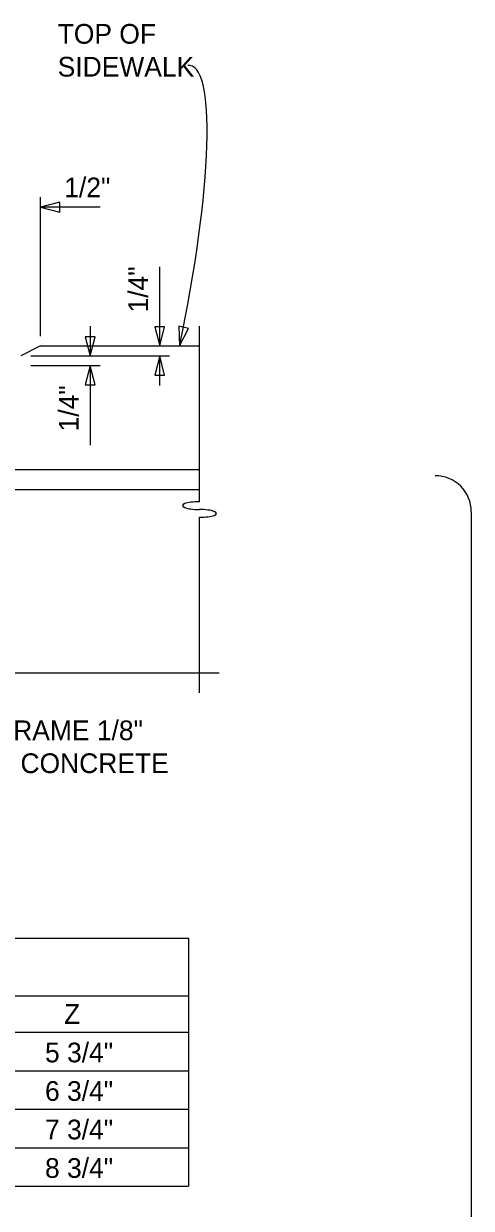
# Model space of a CAD drawing. Extents: x 19590 to 20151, y 19944 to 20103.
# Drawn here: x 19703.76 to 19715.03, y 20049.76 to 20079.64 of the extents above; entities that cross this region are included whole.
import ezdxf

# ---------------------------------------------------------------- set-up
doc = ezdxf.new("R2010")
doc.units = 0
for name, color, linetype in [('DETAIL_PR', 7, 'Continuous'), ('DETAIL_TEXT_DIMEN_PR', 7, 'Continuous'), ('Level 1', 7, 'Continuous')]:
    doc.layers.add(name, color=color, linetype=linetype)

# ---------------------------------------------------------------- blocks, each defined once
blk = doc.blocks.new('BRE')
at = {"layer": 'DETAIL_PR'}
for centre, ratio, start_param, end_param in [((0, 0.098), 0.230206, 4.712389, 7.853982), ((0, -0.098), 0.230204, 1.570796, 4.712389)]:
    blk.add_ellipse(centre, major_axis=(-0.427, 0), ratio=ratio, start_param=start_param, end_param=end_param, dxfattribs=at)

msp = doc.modelspace()

# ---------------------------------------------------------------- linework, layer by layer
at = {"layer": 'DETAIL_PR'}
for p, q in [((19704.186, 20071.509), (19703.686, 20071.259)), ((19704.186, 20071.509), (19703.686, 20071.259)), ((19704.186, 20071.509), (19708.186, 20071.509)), ((19704.186, 20071.509), (19708.186, 20071.509)), ((19708.186, 20068.384), (19699.129, 20068.384)), ((19708.186, 20068.384), (19699.129, 20068.384)), ((19708.186, 20067.884), (19699.629, 20067.884)), ((19708.186, 20067.884), (19699.629, 20067.884))]:
    msp.add_line(p, q, dxfattribs=at)
at = {"layer": 'DETAIL_TEXT_DIMEN_PR'}
for p, q in [((19704.186, 20071.759), (19704.186, 20075.259)), ((19704.186, 20071.759), (19704.186, 20075.259)), ((19704.668, 20075.133), (19704.186, 20075.009)), ((19704.668, 20075.133), (19704.186, 20075.009)), ((19704.668, 20074.884), (19704.668, 20075.133)), ((19704.668, 20074.884), (19704.668, 20075.133)), ((19704.186, 20075.009), (19704.668, 20074.884)), ((19704.186, 20075.009), (19704.668, 20074.884)), ((19707.061, 20071.991), (19707.186, 20071.509)), ((19707.31, 20071.991), (19707.061, 20071.991)), ((19707.061, 20071.991), (19707.186, 20071.509)), ((19707.31, 20071.991), (19707.061, 20071.991)), ((19707.186, 20071.509), (19707.31, 20071.991)), ((19707.186, 20071.509), (19707.31, 20071.991)), ((19707.664, 20072.006), (19707.686, 20071.509)), ((19707.908, 20071.954), (19707.664, 20072.006)), ((19707.664, 20072.006), (19707.686, 20071.509)), ((19707.908, 20071.954), (19707.664, 20072.006)), ((19707.686, 20071.509), (19707.908, 20071.954)), ((19707.686, 20071.509), (19707.908, 20071.954)), ((19708.186, 20068.582), (19708.186, 20072.009)), ((19708.186, 20067.582), (19708.186, 20072.009)), ((19708.186, 20068.582), (19708.186, 20072.009)), ((19708.186, 20067.582), (19708.186, 20072.009)), ((19705.311, 20071.741), (19705.436, 20071.259)), ((19705.56, 20071.741), (19705.311, 20071.741)), ((19705.311, 20071.741), (19705.436, 20071.259)), ((19705.56, 20071.741), (19705.311, 20071.741)), ((19705.436, 20071.259), (19705.56, 20071.741)), ((19705.436, 20071.259), (19705.56, 20071.741)), ((19703.936, 20071.259), (19707.436, 20071.259)), ((19703.936, 20071.259), (19707.436, 20071.259)), ((19707.186, 20071.259), (19707.061, 20070.777)), ((19707.186, 20071.259), (19707.061, 20070.777)), ((19707.31, 20070.777), (19707.186, 20071.259)), ((19707.31, 20070.777), (19707.186, 20071.259)), ((19705.686, 20071.009), (19703.936, 20071.009)), ((19705.686, 20071.009), (19703.936, 20071.009)), ((19705.436, 20071.009), (19705.311, 20070.527)), ((19705.436, 20071.009), (19705.311, 20070.527)), ((19705.56, 20070.527), (19705.436, 20071.009)), ((19705.56, 20070.527), (19705.436, 20071.009)), ((19707.061, 20070.777), (19707.31, 20070.777)), ((19707.061, 20070.777), (19707.31, 20070.777)), ((19705.311, 20070.527), (19705.56, 20070.527)), ((19705.311, 20070.527), (19705.56, 20070.527)), ((19708.186, 20062.762), (19708.186, 20067.189)), ((19708.186, 20062.762), (19708.186, 20067.189)), ((19715.034, 20067.326), (19715.034, 20046.412)), ((19700.632, 20063.262), (19708.686, 20063.262)), ((19700.632, 20063.262), (19708.686, 20063.262)), ((19681.908, 20056.576), (19707.908, 20056.576)), ((19681.908, 20056.576), (19707.908, 20056.576)), ((19707.908, 20056.576), (19707.908, 20050.319)), ((19707.908, 20056.576), (19707.908, 20050.319)), ((19681.917, 20055.119), (19707.908, 20055.119)), ((19681.917, 20055.119), (19707.908, 20055.119)), ((19681.908, 20054.202), (19707.908, 20054.202)), ((19681.908, 20054.202), (19707.908, 20054.202)), ((19681.908, 20053.231), (19707.908, 20053.231)), ((19681.908, 20053.231), (19707.908, 20053.231)), ((19681.908, 20052.26), (19707.908, 20052.26)), ((19681.908, 20052.26), (19707.908, 20052.26)), ((19681.908, 20051.289), (19707.908, 20051.289)), ((19681.908, 20051.289), (19707.908, 20051.289)), ((19681.908, 20050.319), (19707.908, 20050.319)), ((19681.908, 20050.319), (19707.908, 20050.319))]:
    msp.add_line(p, q, dxfattribs=at)
msp.add_arc((19714.125, 20067.327), 0.91, 359.9663, 90.0337, dxfattribs=at)
at = {"layer": 'Level 1'}
for p, q in [((19705.686, 20075.009), (19704.186, 20075.009)), ((19705.686, 20075.009), (19704.186, 20075.009)), ((19707.186, 20071.509), (19707.186, 20073.509)), ((19707.186, 20071.509), (19707.186, 20073.509)), ((19705.436, 20072.009), (19705.436, 20071.259)), ((19705.436, 20072.009), (19705.436, 20071.259)), ((19707.186, 20070.509), (19707.186, 20071.259)), ((19707.186, 20070.509), (19707.186, 20071.259)), ((19705.436, 20071.009), (19705.436, 20069.009)), ((19705.436, 20071.009), (19705.436, 20069.009))]:
    msp.add_line(p, q, dxfattribs=at)
msp.add_ellipse((19706.481, 20071.629), major_axis=(1.489, 6.95), ratio=0.169331, start_param=4.731306, end_param=6.346137, dxfattribs=at)
msp.add_ellipse((19706.481, 20071.629), major_axis=(1.489, 6.95), ratio=0.169331, start_param=4.731306, end_param=6.346137, dxfattribs=at)

# ---------------------------------------------------------------- block references
at = {"layer": 'Level 1', "rotation": 180}
msp.add_blockref('BRE', (19708.186, 20067.385), dxfattribs=at)
msp.add_blockref('BRE', (19708.186, 20067.385), dxfattribs=at)

# ---------------------------------------------------------------- texts
at = {"layer": 'DETAIL_TEXT_DIMEN_PR'}
for s, height, p in [('TOP OF', 0.4976, (19704.616, 20079.133)), ('TOP OF', 0.4976, (19704.616, 20079.133)), ('SIDEWALK', 0.4976, (19704.616, 20078.304)), ('SIDEWALK', 0.4976, (19704.616, 20078.304)), ('PLACE STEEL FRAME 1/8" ', 0.49762, (19698.429, 20061.566)), ('PLACE STEEL FRAME 1/8" ', 0.49762, (19698.429, 20061.566)), ('BELOW TOP OF CONCRETE', 0.49762, (19698.429, 20060.737)), ('BELOW TOP OF CONCRETE', 0.49762, (19698.429, 20060.737))]:
    msp.add_text(s, height=height, dxfattribs=at).set_placement(p)
for s, height, rotation, p in [('1/2"', 0.4976, 360, (19704.782, 20075.26)), ('1/2"', 0.4976, 360, (19704.782, 20075.26)), ('1/4"', 0.4976, 90, (19706.893, 20072.355)), ('1/4"', 0.4976, 90, (19706.893, 20072.355)), ('1/4"', 0.4976, 90, (19705.143, 20069.355)), ('1/4"', 0.4976, 90, (19705.143, 20069.355)), ('Z', 0.498, 0, (19704.777, 20054.412)), ('Z', 0.498, 0, (19704.777, 20054.412)), ('5 3/4"', 0.4976, 0, (19704.297, 20053.441)), ('5 3/4"', 0.4976, 0, (19704.297, 20053.441)), ('6 3/4"', 0.4976, 0, (19704.297, 20052.47)), ('6 3/4"', 0.4976, 0, (19704.297, 20052.47)), ('7 3/4"', 0.4976, 0, (19704.297, 20051.499)), ('7 3/4"', 0.4976, 0, (19704.297, 20051.499)), ('8 3/4"', 0.4976, 0, (19704.297, 20050.528)), ('8 3/4"', 0.4976, 0, (19704.297, 20050.528))]:
    msp.add_text(s, height=height, rotation=rotation, dxfattribs=at).set_placement(p)

doc.saveas('drawing.dxf')
